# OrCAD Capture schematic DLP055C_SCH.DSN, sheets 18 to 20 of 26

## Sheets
18 P08 - DLPC MISC: size A3
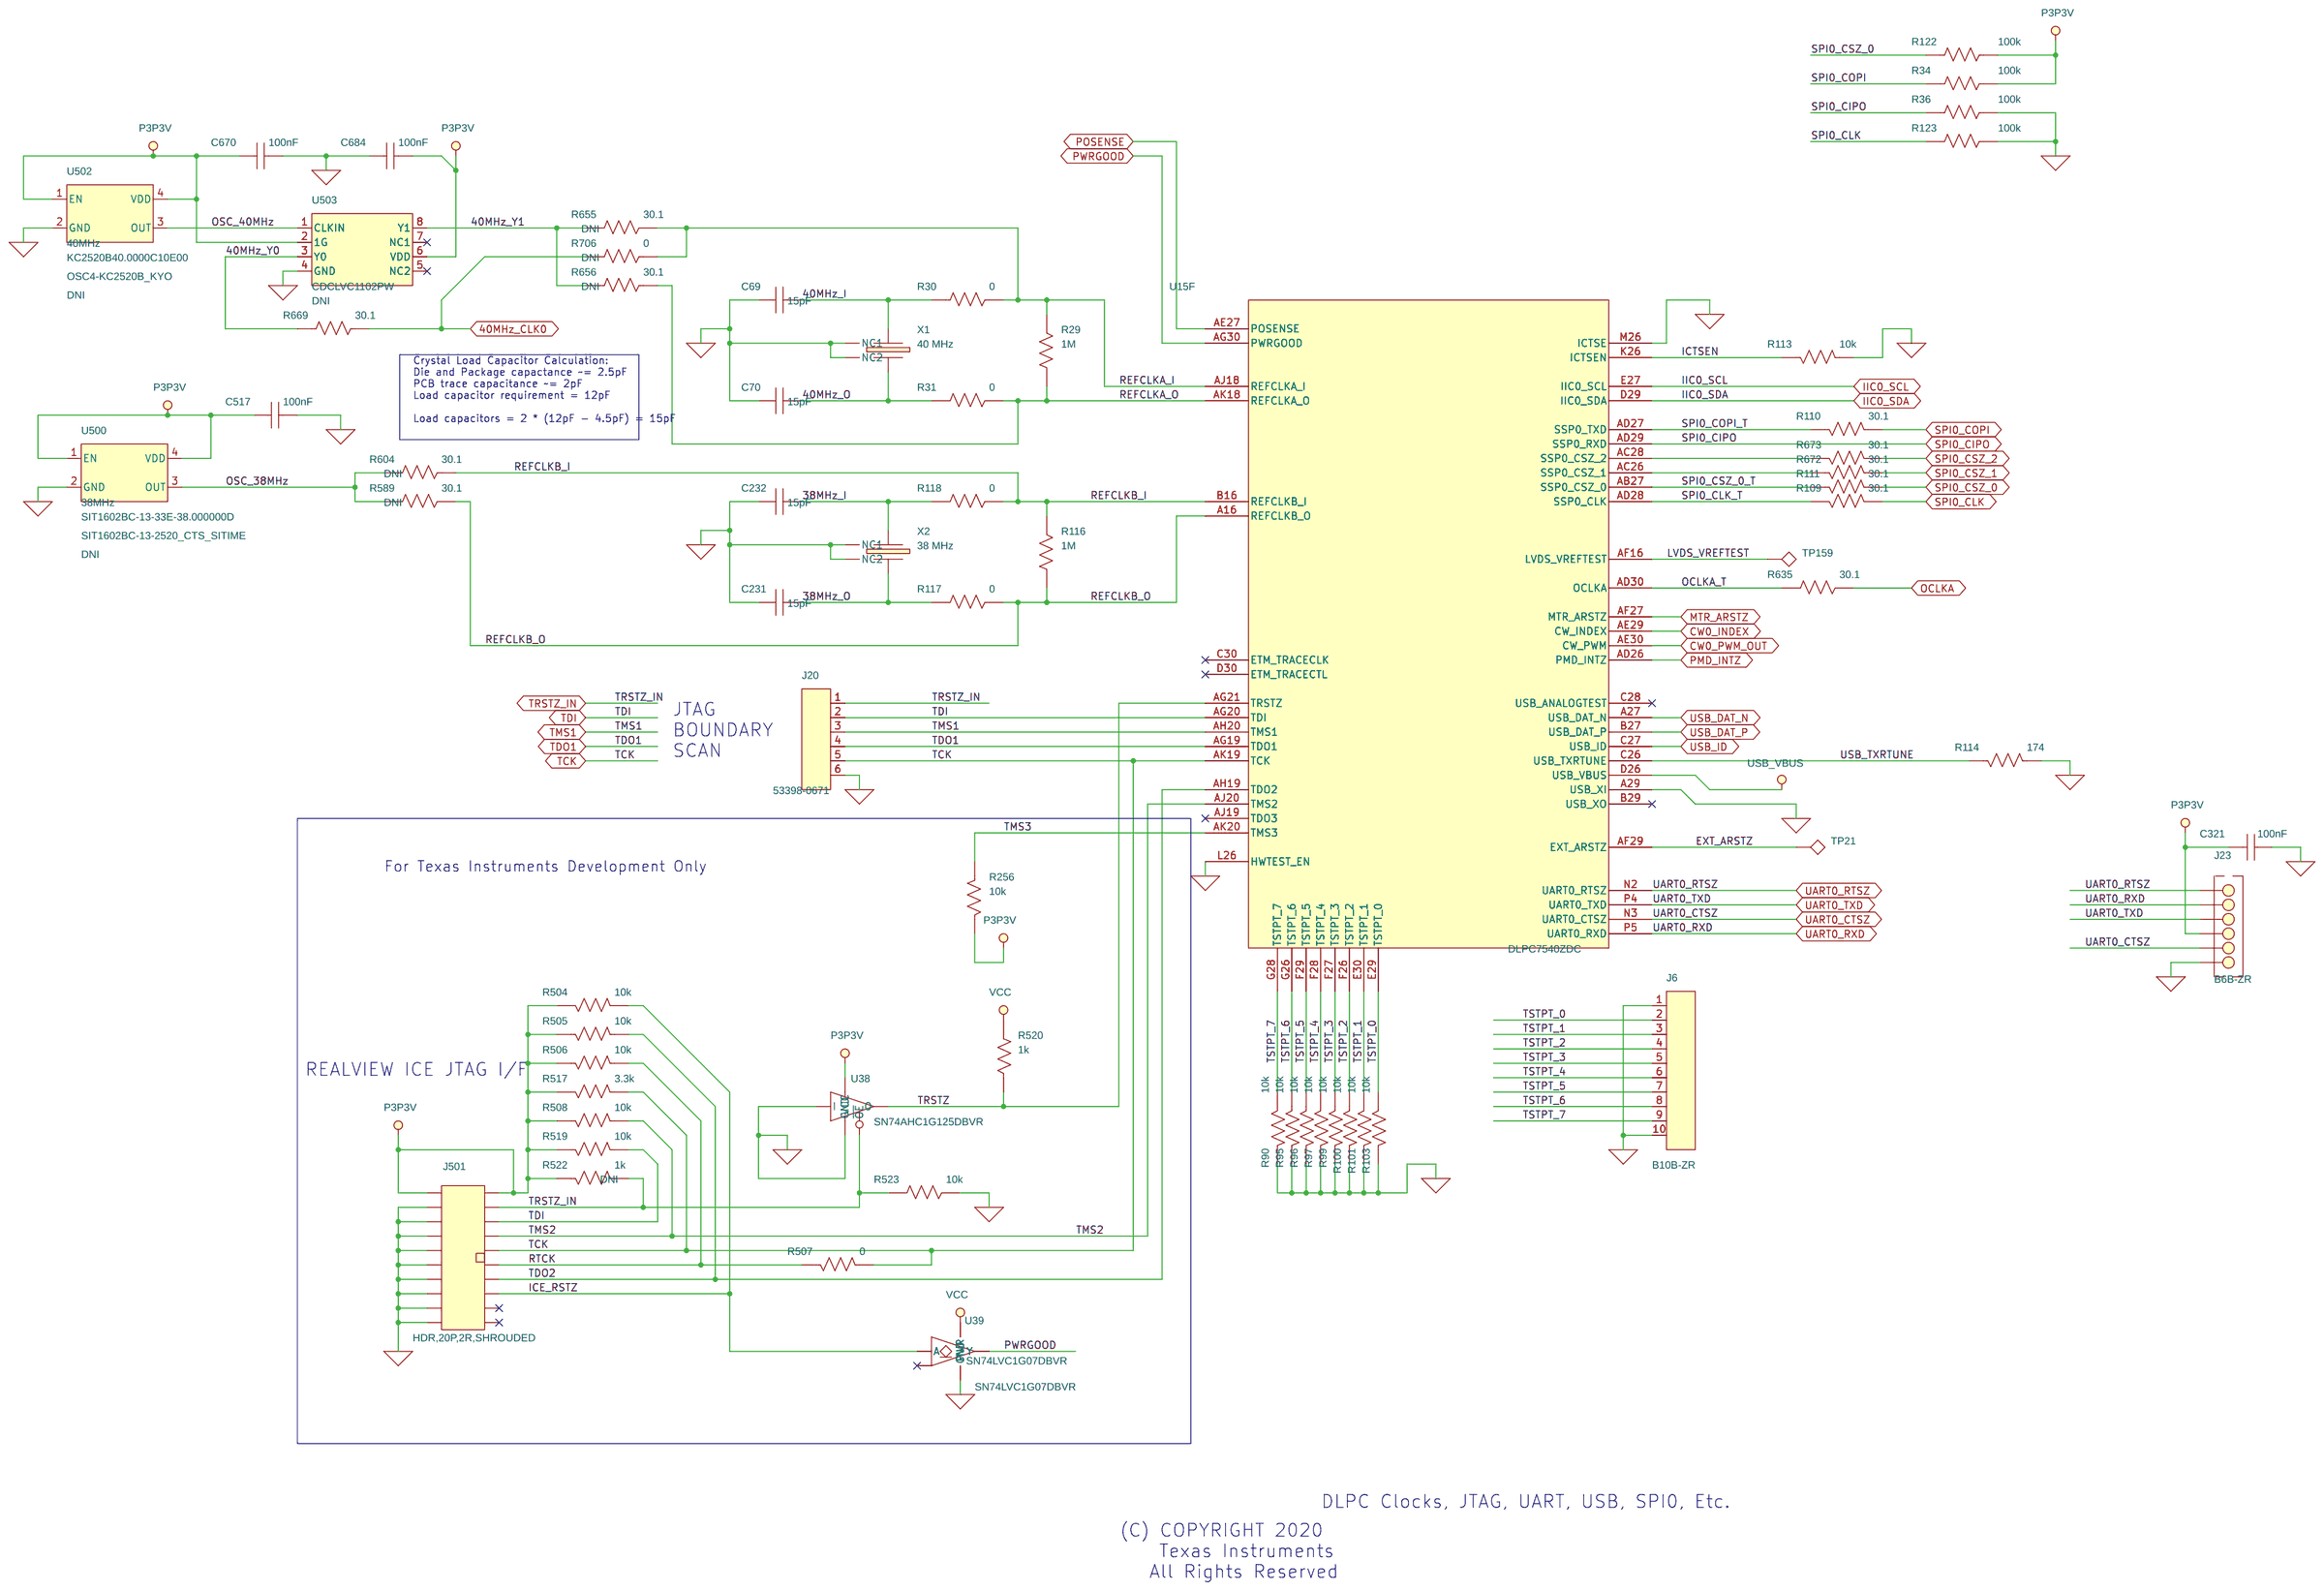
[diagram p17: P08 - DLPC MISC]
19 P12 - IIC, SPI, USB & EEPROM: size A3
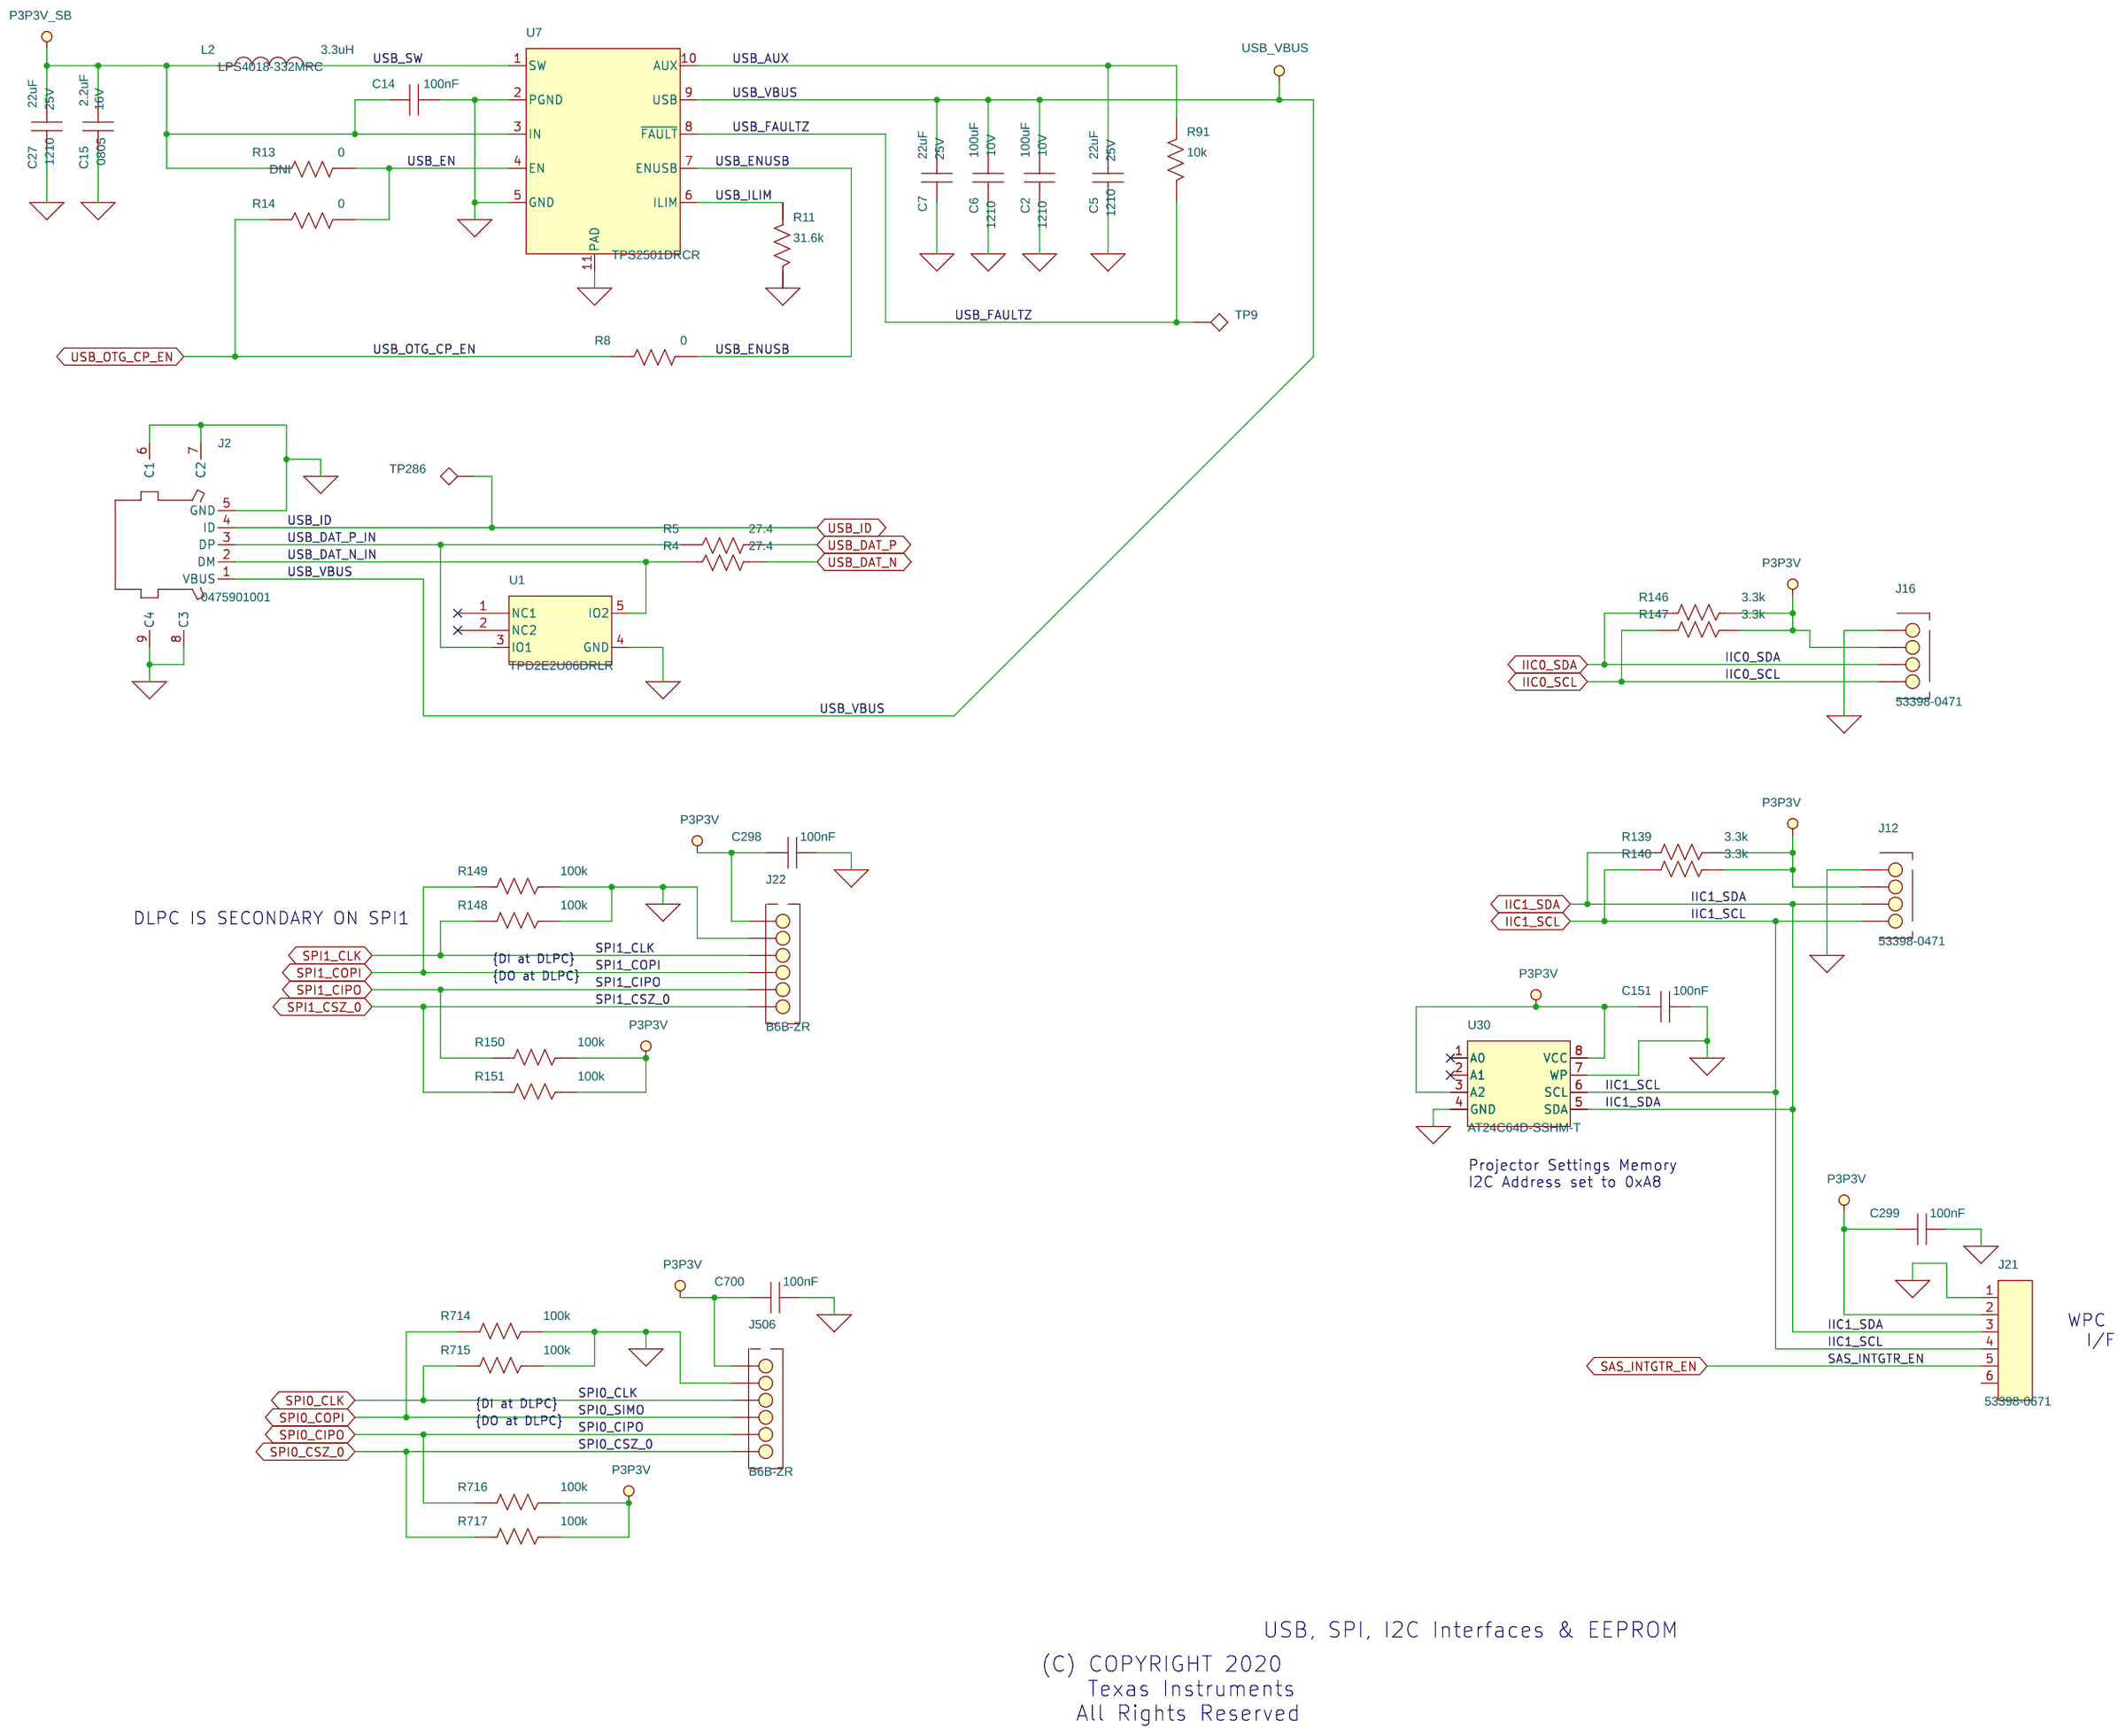
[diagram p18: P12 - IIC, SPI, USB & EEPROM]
20 P09 - DLPC GPIO: size A3
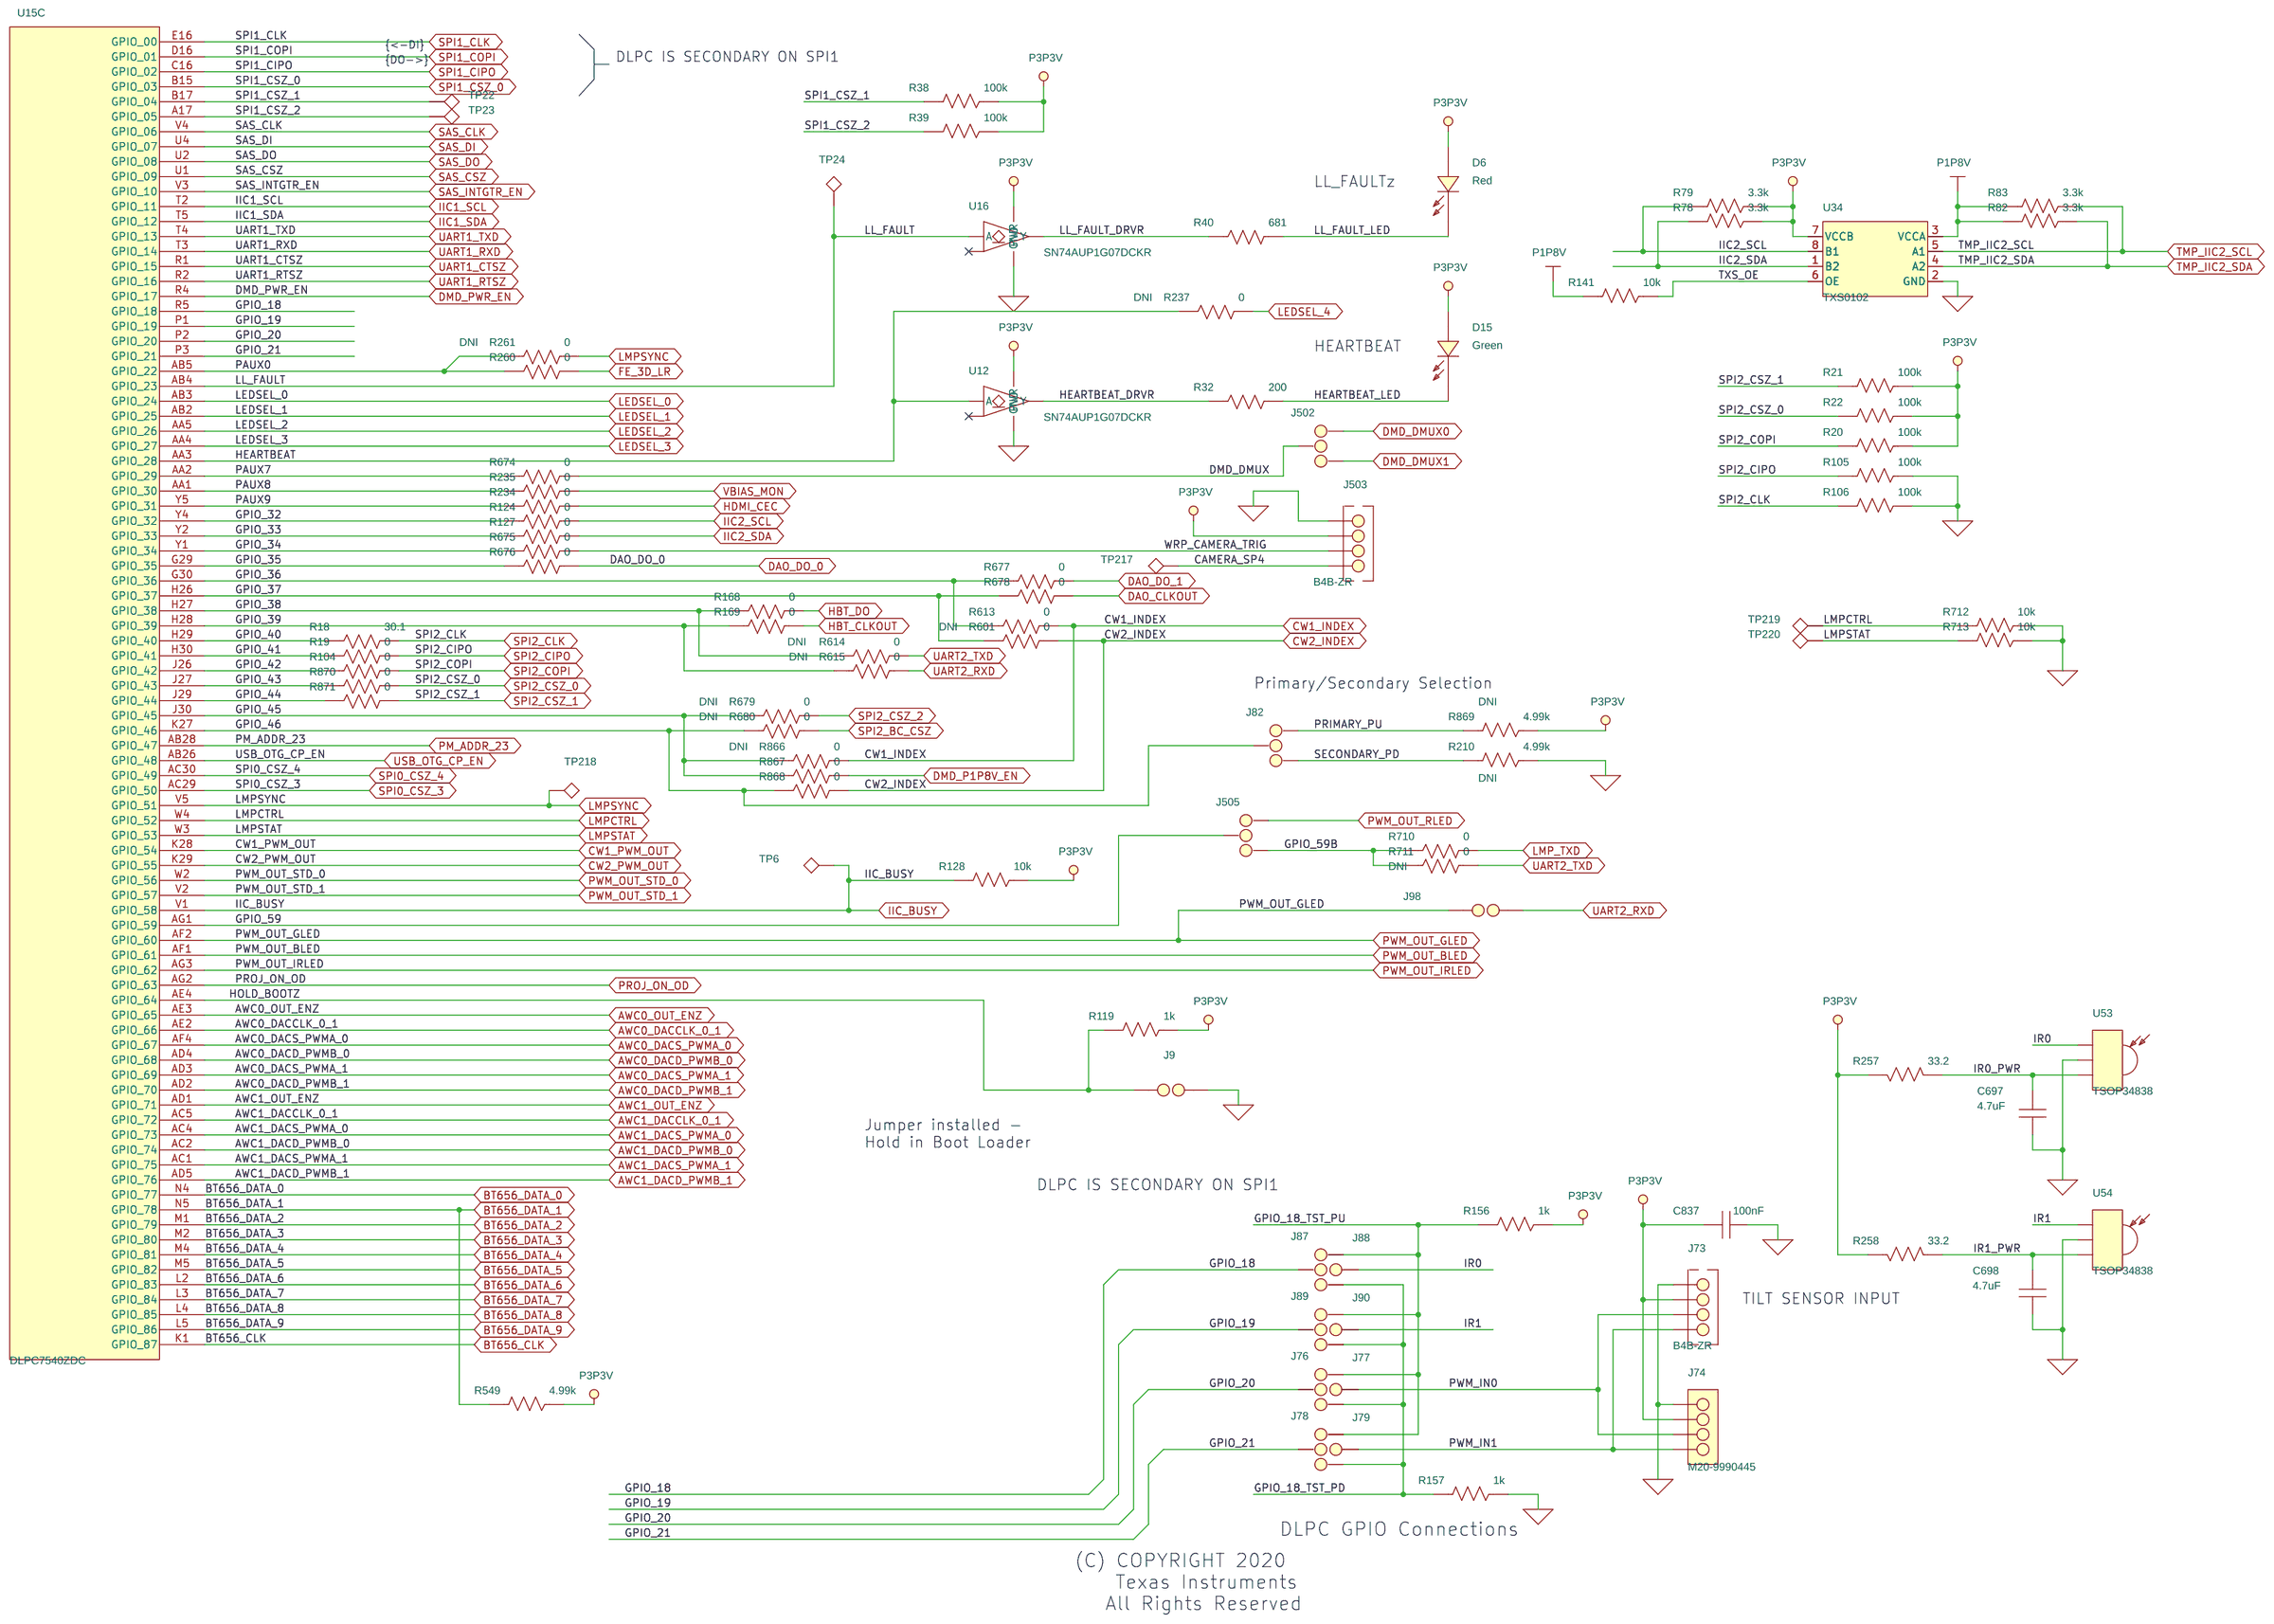
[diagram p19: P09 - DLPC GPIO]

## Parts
sheet P08 - DLPC MISC
C69  15pF  [0402]
C70  15pF  [0402]
C231  15pF  [0402]
C232  15pF  [0402]
C321  100nF  [0402]
C517  100nF  [0402]
C670  100nF  [0402]
C684  100nF  [0402]
J6  B10B-ZR  [JST_B10B-ZR]
J20  53398-0671  [CONN6-53398-0690_MOLEX]
J23  B6B-ZR  [HDR1X6-B6B-ZR_JST]
J501  HDR,20P,2R,SHROUDED  [HDR10X2-5103308_TYCO]
R29  1M  [0402]
R30  0  [0402]
R31  0  [0402]
R34  100k  [0402]
R36  100k  [0402]
R90  10k  [0402]
R95  10k  [0402]
R96  10k  [0402]
R97  10k  [0402]
R99  10k  [0402]
R100  10k  [0402]
R101  10k  [0402]
R103  10k  [0402]
R109  30.1  [0402]
R110  30.1  [0402]
R111  30.1  [0402]
R113  10k  [0402]
R114  174  [0402]
R116  1M  [0402]
R117  0  [0402]
R118  0  [0402]
R122  100k  [0402]
R123  100k  [0402]
R256  10k  [0402]
R504  10k  [0402]
R505  10k  [0402]
R506  10k  [0402]
R507  0  [0402]
R508  10k  [0402]
R517  3.3k  [0402]
R519  10k  [0402]
R520  1k  [0402]
R522  1k  [0402]
R523  10k  [0402]
R589  30.1  [0402]
R604  30.1  [0402]
R635  30.1  [0402]
R655  30.1  [0402]
R656  30.1  [0402]
R669  30.1  [0402]
R672  30.1  [0402]
R673  30.1  [0402]
R706  0  [0402]
TP21  TP,28mil Drill,48mil Pad  [HTP-48RD28]
TP159  TP,28mil Drill,48mil Pad  [HTP-48RD28]
U38  SN74AHC1G125DBVR  [SOIC5-SOT-23_DBV-TI]
U39  SN74LVC1G07DBVR  [SOIC5-SOT-23_DBV-TI]
U500  38MHz  [SIT1602BC-13-2520_CTS_SITIME]
U502  40MHz  [OSC4-KC2520B_KYO]
U503  CDCLVC1102PW  [SOIC8-PW_TI]
X1  40 MHz  [TXC_TM3225]
X2  38 MHz  [TXC_TM3225]
sheet P09 - DLPC GPIO
C697  4.7uF  [0805]
C698  4.7uF  [0805]
C837  100nF  [0402]
D6  Red  [LED-LTST-C190_LITEON]
D15  Green  [LED-LTST-C190_LITEON]
J9  HDR,2P,1R  [HDR2P_1R]
J73  B4B-ZR  [HDR1X4-B4B-ZR_JST]
J74  HDR,4P,1R  [HDR1X4]
J76  HDR,3P,1R  [HDR1X3]
J77  HDR,1P,1R  [HDR1]
J78  HDR,3P,1R  [HDR1X3]
J79  HDR,1P,1R  [HDR1]
J82  HDR,3P,1R  [HDR1X3]
J87  HDR,3P,1R  [HDR1X3]
J88  HDR,1P,1R  [HDR1]
J89  HDR,3P,1R  [HDR1X3]
J90  HDR,1P,1R  [HDR1]
J98  HDR,2P,1R  [HDR2P_1R]
J502  HDR,3P,1R  [HDR1X3]
J503  B4B-ZR  [HDR1X4-B4B-ZR_JST]
J505  HDR,3P,1R  [HDR1X3]
R18  30.1  [0402]
R19  0  [0402]
R20  100k  [0402]
R21  100k  [0402]
R22  100k  [0402]
R32  200  [0402]
R38  100k  [0402]
R39  100k  [0402]
R40  681  [0402]
R78  3.3k  [0402]
R79  3.3k  [0402]
R82  3.3k  [0402]
R83  3.3k  [0402]
R104  0  [0402]
R105  100k  [0402]
R106  100k  [0402]
R119  1k  [0402]
R124  0  [0402]
R127  0  [0402]
R128  10k  [0402]
R141  10k  [0402]
R156  1k  [0402]
R157  1k  [0402]
R168  0  [0402]
R169  0  [0402]
R210  4.99k  [0402]
R234  0  [0402]
R235  0  [0402]
R237  0  [0402]
R257  33.2  [0402]
R258  33.2  [0402]
R260  0  [0402]
R261  0  [0402]
R549  4.99k  [0402]
R601  0  [0402]
R613  0  [0402]
R614  0  [0402]
R615  0  [0402]
R674  0  [0402]
R675  0  [0402]
R676  0  [0402]
R677  0  [0402]
R678  0  [0402]
R679  0  [0402]
R680  0  [0402]
R710  0  [0402]
R711  0  [0402]
R712  10k  [0402]
R713  10k  [0402]
R866  0  [0402]
R867  0  [0402]
R868  0  [0402]
R869  4.99k  [0402]
R870  0  [0402]
R871  0  [0402]
TP6  TP,28mil Drill,48mil Pad  [HTP-48RD28]
TP22  TP,20mil PAD  [20mil_PAD]
TP23  TP,20mil PAD  [20mil_PAD]
TP24  TP,28mil Drill,48mil Pad  [HTP-48RD28]
TP217  TP,20mil PAD  [20mil_PAD]
TP218  TP,28mil Drill,48mil Pad  [HTP-48RD28]
TP219  TP,28mil Drill,48mil Pad  [HTP-48RD28]
TP220  TP,28mil Drill,48mil Pad  [HTP-48RD28]
U12  SN74AUP1G07DCK  [U_5_DCK]
U15  TIDLP,DLPC7540  [DLPC7540_HBGA676_3131]  (sections A,B,C,D,E,F,G,H,I)
U16  SN74AUP1G07DCK  [U_5_DCK]
U34  TXS0102  [VSSOP-8_DCU]
U53  TSOP34838  [IR3-TSOP34_VIS]
U54  TSOP34838  [IR3-TSOP34_VIS]
sheet P12 - IIC, SPI, USB & EEPROM
C2  100uF  [1210]
C5  22uF  [1210]
C6  100uF  [1210]
C7  22uF  [1210]
C14  100nF  [0402]
C15  2.2uF  [0805]
C27  22uF  [1210]
C151  100nF  [0402]
C298  100nF  [0402]
C299  100nF  [0402]
C700  100nF  [0402]
J2  USB,TYPE AB,MICRO,TOP MNT  [Molex_0475901001]
J12  53398-0471  [CONN4-53398_MOLEX]
J16  53398-0471  [CONN4-53398_MOLEX]
J21  53398-0671  [CONN6-53398-0690_MOLEX]
J22  B6B-ZR  [HDR1X6-B6B-ZR_JST]
J506  B6B-ZR  [HDR1X6-B6B-ZR_JST]
L2  3.3uH  [Coilcraft_LPS4018]
R4  27.4  [0402]
R5  27.4  [0402]
R8  0  [0402]
R11  31.6k  [0402]
R13  0  [0402]
R14  0  [0402]
R91  10k  [0402]
R139  3.3k  [0402]
R140  3.3k  [0402]
R146  3.3k  [0402]
R147  3.3k  [0402]
R148  100k  [0402]
R149  100k  [0402]
R150  100k  [0402]
R151  100k  [0402]
R714  100k  [0402]
R715  100k  [0402]
R716  100k  [0402]
R717  100k  [0402]
TP9  TP,28mil Drill,48mil Pad  [HTP-48RD28]
TP286  TP,28mil Drill,48mil Pad  [HTP-48RD28]
U1  TPD2E2U06DRL  [SOT-5_DRL_R-PDSO-N5]
U7  TPS2501DRCR  [TI_DRC0010J_VSON-10]
U30  AT24C64D-SSHM-T  [SOIC8]

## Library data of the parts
C69 C70 C231 C232 = PAS,CAP,NP: ALT_SYMBOLS: 0402_1mm; CCA: 9; DigiKey: 1276-1179-1-ND; DigiReel: 1276-1179-6-ND; Family: passive; Index PN: 1567; Install: Y; Lead Style: SMT; MFG: Samsung; Material: npo; P/D_NUM: CL05C150JB5NNNC; Part Number: CL05C150JB5NNNC; Part Specific: CAP CER 15PF 50V C0G/NP0 0402; TOLERANCE: 5%; Type: capacitor; VPC: 50V; Vendor: Samsung; Voltage: 50V
C14 C151 C298 C299 C321 C700 = PAS,CAP,NP: ALT_SYMBOLS: 0402_1mm; DigiKey: 587-3499-1-ND; DigiReel: 587-3499-6-ND; Family: passive; Index PN: 1280; Install: Y; Lead Style: SMT; MFG: Taiyo Yuden; Material: x5r; P/D_NUM: UMK105BJ104KV-F; Part Number: UMK105BJ104KV-F; Part Specific: CAP CER 0.1UF 50V 10% X5R 0402; TOLERANCE: 10%; Type: capacitor; VPC: 50V; Vendor: Taiyo Yuden
C517 = PAS,CAP,NP: ALT_SYMBOLS: 0402_1mm; CCA: 9; DigiKey: 587-3499-1-ND; Family: passive; Index PN: 1280; Install: Y; Lead Style: SMT; MFG: Taiyo Yuden; Material: x5r; P/D_NUM: UMK105BJ104KV-F; Part Number: UMK105BJ104KV-F; Part Specific: CAP CER 0.1UF 50V 10% X5R 0402; RATING: <RATING>; TOLERANCE: 10%; Type: capacitor; VPC: 50V; Vendor: Taiyo Yuden
C670 C684 = PAS,CAP,NP: ALT_SYMBOLS: 0402_1mm; CCA: 9; DigiKey: 587-3499-1-ND; Family: passive; Index PN: 1280; Install: Y; Lead Style: SMT; MFG: Taiyo Yuden; Material: x5r; P/D_NUM: UMK105BJ104KV-F; Part Number: UMK105BJ104KV-F; Part Specific: CAP CER 0.1UF 50V 10% X5R 0402; TOLERANCE: 10%; Type: capacitor; VPC: 50V; Vendor: Taiyo Yuden
J6 = EM,HDR,10P,1R: DigiKey: 455-1665-ND; Family: electro/mechanical; Index PN: 1120; Install: Y; Lead Style: TH; MFG: JST; P/D_NUM: B10B-ZR(LF)(SN); Part Number: B10B-ZR(LF)(SN); Part Specific: CONN HEADER ZH TOP 10POS 1.5MM; Pin Cnt: 10; Pin Spacing: 1.5mm; Row Cnt: 1; Vendor: JST
J20 J21 = EM,HDR,6P,1R: DigiKey: WM7610CT-ND; DigiReel: WM7610DKR-ND; Family: electro/mechanical; Index PN: 1521; Install: Y; Lead Style: SMT; MFG: Molex; Part Specific: CONN HEADER 6POS 1.25MM VERT SMD; Pin Cnt: 6; Pin Spacing: 1.25mm; Row Cnt: 1; Type: connector; Vendor: Molex
J23 = EM,HDR,6P,1R,1x,B6B-EH: DigiKey: 455-1661-ND; DigiReel: ---; Family: electro/mechanical; Index PN: 1663; Lead Style: TH; MFG: JST; P/D_NUM: B6B-ZR(LF)(SN); Part Number: B6B-ZR(LF)(SN); Part Specific: CONN HEADER VERT 6POS 1.5MM; Pin Cnt: 6; Pin Spacing: 1.5mm; Row Cnt: 1; Type: connector; Vendor: JST
J501 = EM,HDR,20P,2R,NARROW_SYM: DigiKey: A33165-ND; Family: electro/mechanical; Index PN: 1093; Lead Style: TH; MFG: Tyco Electronics; P/D_NUM: 5103308-5; Part Number: 5103308-5; Part Specific: CONN HEADER LOPRO STR 14POS GOLD; Pin Cnt: 14; Pin Spacing: 100x100mil; Row Cnt: 2; Type: header; Vendor: Tyco Electronics
R29 R116 = PAS,R,large: ALT_SYMBOLS: 0402_1mm; DigiKey: P1.00MLCT-ND; Family: passive; Index PN: 1229; Lead Style: SMT; MFG: Panasonic; Material: chip; P/D_NUM: ERJ-2RKF1004X; Part Number: ERJ-2RKF1004X; Part Specific: RES 1M OHM 1/10W 1% 0402 SMD; TOLERANCE: 1%; Type: resistor; VENDOR: Panasonic; VPC: 1/10W
R30 R31 R117 R118 = PAS,R,large: ALT_SYMBOLS: 0402_1mm; DigiKey: P0.0JCT-ND; DigiReel: P0.0JDKR-ND; Family: passive; Index PN: 687; Lead Style: SMT; MFG: Panasonic; Material: chip; P/D_NUM: ERJ-2GE0R00X; Part Number: ERJ-2GE0R00X; Part Specific: RES 0.0 OHM 1/16W 0402 SMD; Power: 1/16W; Type: resistor; VENDOR: Panasonic; VPC: 1/16W
R20-R22 R34 R36 R38 R39 R105 R106 R122 R123 R148-R151 R714-R717 = PAS,R,large: ALT_SYMBOLS: 0402_1mm; DigiKey: 311-100KLRCT-ND; DigiReel: 311-100KLRDKR-ND; Family: passive; Lead Style: SMT; MFG: Yageo; Material: chip; P/D_NUM: RC0402FR-07100KL; Part Number: RC0402FR-07100KL; Part Specific: RES 100K OHM 1/10W 1% 0402 SMD; Power: 1/16W; Tolerance: 1%; Type: resistor; VPC: 1/16W; Vendor: Yageo
R90 R91 R95-R97 R99-R101 R103 R113 = PAS,R,large: ALT_SYMBOLS: 0402_1mm; CCA: 65; DigiKey: 311-10.0KLRCT-ND; DigiReel: 311-10.0KLRDKR-ND; Family: passive; ICA_MFR_NAME: PANASONIC; ICA_PARTNUM: $$1785048$$ERJ-3GSYJ102; Index PN: 680; Install: Y; Lead Style: SMT; MFG: Yageo; Material: chip; P/D_NUM: RC0402FR-0710KL; Part Number: RC0402FR-0710KL; Part Specific: RES 10K OHM 1% 1/16W 0402 SMD; Power: 1/16W; TOLERANCE: 1%; Type: resistor; VPC: 1/16W; Vendor: Yageo
R109-R111 R672 R673 = PAS,R,large: ALT_SYMBOLS: 0402_1mm; DigiKey: YAG3111CT-ND; Family: passive; Index PN: 976; Lead Style: SMT; MFG: Yageo; Material: chip; P/D_NUM: RC0402FR-0730R1L; Part Number: RC0402FR-0730R1L; Part Specific: RES 30.1 OHM 1/16W 1% 0402 SMD; Power: 1/16W; TOLERANCE: 1%; Type: resistor; VENDOR: Yageo; VPC: 1/16W
R114 = PAS,R,large: ALT_SYMBOLS: 0402_1mm; DigiKey: YAG3009CT-ND; DigiReel: YAG3009DKR-ND; Family: passive; Index PN: 1701; Lead Style: SMT; MFG: Yageo; P/D_NUM: RC0402FR-07174RL; Part Number: RC0402FR-07174RL; Part Specific: RES 174 OHM 1% 1/16W 0402 SMD; TOLERANCE: 1%; Type: resistor; VENDOR: Yageo; VPC: 1/16W
R256 R504-R506 R508 R519 R523 = PAS,R,large: ALT_SYMBOLS: 0402_1mm; CCA: 65; DigiKey: 311-10.0KLRCT-ND; Family: passive; ICA_MFR_NAME: PANASONIC; ICA_PARTNUM: $$1785048$$ERJ-3GSYJ102; Index PN: 680; Install: Y; Lead Style: SMT; MFG: Yageo; Material: chip; P/D_NUM: RC0402FR-0710KL; Part Number: RC0402FR-0710KL; Power: 1/16W; TOLERANCE: 1%; Type: resistor; VPC: 1/16W; Vendor: Yageo
R507 = PAS,R,large: ALT_SYMBOLS: 0402_1mm; CCA: 64; DigiKey: P0.0JCT-ND; Family: passive; ICA_MFR_NAME: PANASONIC; ICA_PARTNUM: $$1785048$$ERJ-3GSYJ102; Index PN: 687; Install: Y; Lead Style: SMT; MFG: Panasonic; Material: chip; P/D_NUM: ERJ-2GE0R00X; Part Number: ERJ-2GE0R00X; Part Specific: RES 0.0 OHM 1/16W 0402 SMD; Power: 1/16W; Type: resistor; VPC: 1/16W; Vendor: Panasonic
R517 = PAS,R,large: ALT_SYMBOLS: 0402_1mm; CCA: 68; DigiKey: P3.3KDCCT-ND; Family: passive; ICA_MFR_NAME: PANASONIC; ICA_PARTNUM: $$1785048$$ERJ-3GSYJ102; Index PN: 1436; Install: Y; Lead Style: SMT; MFG: Panasonic; Material: chip; P/D_NUM: ERA-2AEB332X; Part Number: ERA-2AEB332X; Part Specific: RES SMD 3.3K OHM 0.1% 1/16W 0402; TOLERANCE: 1%; Type: resistor; VPC: 1/16W; Vendor: Panasonic
R520 = PAS,R,large: ALT_SYMBOLS: 0402_1mm; CCA: 64; DigiKey: 311-1.00KLRCT-ND; Family: passive; ICA_MFR_NAME: PANASONIC; ICA_PARTNUM: $$1785048$$ERJ-3GSYJ102; Index PN: 684; Install: Y; Lead Style: SMT; MFG: Yageo; Material: chip; P/D_NUM: RC0402FR-071KL; Part Number: RC0402FR-071KL; Part Specific: RES 1.00K OHM 1/10W 1% 0402 SMD; Power: 1/16W; TOLERANCE: 1%; Type: resistor; VPC: 1/16W; Vendor: Yageo
R522 = PAS,R,large: ALT_SYMBOLS: 0402_1mm; CCA: 64; DigiKey: 311-1.00KLRCT-ND; Family: passive; ICA_MFR_NAME: PANASONIC; ICA_PARTNUM: $$1785048$$ERJ-3GSYJ102; Index PN: 684; Install: DNI; Lead Style: SMT; MFG: Yageo; Material: chip; P/D_NUM: RC0402FR-071KL; Part Number: RC0402FR-071KL; Part Specific: RES 1.00K OHM 1/10W 1% 0402 SMD; Power: 1/16W; TOLERANCE: 1%; Type: resistor; VPC: 1/16W; Vendor: Yageo
R589 R604 R655 R656 = PAS,R,large: ALT_SYMBOLS: 0402_1mm; DigiKey: YAG3111CT-ND; Family: passive; Index PN: 976; Install: DNI; Lead Style: SMT; MFG: Yageo; Material: chip; P/D_NUM: RC0402FR-0730R1L; Part Number: RC0402FR-0730R1L; Part Specific: RES 30.1 OHM 1/16W 1% 0402 SMD; Power: 1/16W; TOLERANCE: 1%; Type: resistor; VENDOR: Yageo; VPC: 1/16W
R635 = PAS,R,large: ALT_SYMBOLS: 0402_1mm; CCA: 67; DigiKey: YAG3111CT-ND; Family: passive; ICA_MFR_NAME: PANASONIC; ICA_PARTNUM: $$1785048$$ERJ-3GSYJ102; Index PN: 976; Install: Y; Lead Style: SMT; MFG: Yageo; Material: chip; P/D_NUM: RC0402FR-0730R1L; Part Number: RC0402FR-0730R1L; Part Specific: RES 30.1 OHM 1/16W 1% 0402 SMD; Power: 1/16W; TOLERANCE: 1%; Type: resistor; VPC: 1/16W; Vendor: Yageo
R669 = PAS,R,large: ALT_SYMBOLS: 0402_1mm; DigiKey: YAG3111CT-ND; Family: passive; Index PN: 976; Install: Y; Lead Style: SMT; MFG: Yageo; Material: chip; P/D_NUM: RC0402FR-0730R1L; Part Number: RC0402FR-0730R1L; Part Specific: RES 30.1 OHM 1/16W 1% 0402 SMD; Power: 1/16W; TOLERANCE: 1%; Type: resistor; VENDOR: Yageo; VPC: 1/16W
R706 = PAS,R,large: ALT_SYMBOLS: 0402_1mm; DigiKey: P0.0JCT-ND; Family: passive; Index PN: 687; Install: DNI; Lead Style: SMT; MFG: Panasonic; Material: chip; P/D_NUM: ERJ-2GE0R00X; Part Number: ERJ-2GE0R00X; Part Specific: RES 0.0 OHM 1/16W 0402 SMD; Power: 1/16W; Type: resistor; VENDOR: Panasonic; VPC: 1/16W
TP6 TP9 TP21 TP24 TP159 TP218-TP220 TP286 = EM,TERM,TESTPOINT: DigiKey: ---; Family: board feature; Index PN: 1498; Install: DNI; Lead Style: TH; MFG: -- NOT A PART --; Part Specific: HOLE PLATED 48mil pad 28mil drill; Type: hole,plated; Vendor: -- NOT A PART --
U38 = LOG,BUF,74LVC1G125,1x: DigiKey: 296-8744-1-ND; Family: logic; Index PN: 648; Install: Y; MFG: Texas Instruments; Part Specific: Buffer Non-Inverting 1 Element 1 Bit per Element Push-Pull Output SOT-23-5; Type: transceiver; Vendor: Texas Instruments
U39 = TMP_30: CCA: 147; DigiKey: 296-8485-1-ND; Family: logic; Index PN: 1491; Install: Y; Lead Style: SMT; MFG: Texas Instruments; Part Specific: IC BUFF/DVR NON-INVERT SOT23-5; Type: buffer; Vendor: Texas Instruments
U500 = ANA,OSC,4P,1X,small: DigiKey: 1473-SIT1602BC-13-33E-38.000000D-ND; Family: analog; Index PN: 1768; Install: DNI; Lead Style: SMT; MFG: CTS; P/D_NUM: SIT1602BC-13-33E-38.000000D; Part Number: SIT1602BC-13-33E-38.000000D; Part Specific: TCXO Oscillators 38.4MHz 3.3Volt +/-1.5ppm -40C +85C; Type: oscillator; Vendor: SiTIME
U502 = ANA,OSC,4P,1X,small: DigiKey: 478-6300-1-ND; Family: analog; Index PN: 1660; Install: DNI; Lead Style: SMT; MFG: Kyocera; P/D_NUM: KC2520B40.0000C10E00; Part Number: KC2520B40.0000C10E00; Part Specific: XTAL OSC XO 40.0000MHZ CMOS SMD; Type: oscillator; Vendor: Kyocera
U503 = INF,CLK_DRVR,CDCLVC1102: DigiKey: 296-27610-1-ND; Family: interface; Index PN: 1477; Install: DNI; Lead Style: SMT; MFG: Texas Instruments; Part Specific: IC CLK BUFFER 1:2 250MHZ 8TSSOP; Type: clock driver; Vendor: Texas Instruments
X1 = 7V-40.000MDDE-T_CUS: DigiKey: ---; DigiReel: ---; Family: passive; Lead Style: SMT; MFG: TXC; Mouser: ---; P/D_NUM: 7V-40.000MDDE-T; Part Number: 7V-40.000MDDE-T; Part Specific: 40 MHZ, 12pF, +/-20PPM/C, SMD-4P; Type: crystal; VENDOR: TXC
X2 = 7V-38.000MAAV-T_CUS: DigiKey: ---; DigiReel: ---; Family: passive; Lead Style: SMT; MFG: TXC; Mouser: ---; P/D_NUM: 7V-38.000MAAV-T; Part Number: 7V-38.000MAAV-T; Part Specific: 38 MHZ, 8pF, +/-30PPM/C, SMD-4P; Type: crystal; VENDOR: TXC
C697 C698 = PAS,CAP,NP: CCA: 42; DigiKey: 1276-1244-1-ND; Family: passive; Index PN: 1400; Install: Y; Lead Style: SMT; MFG: Samsung; Material: x5r; P/D_NUM: CL21A475KAQNNNE; Part Number: CL21A475KAQNNNE; Part Specific: CAP CER 4.7UF 25V X5R 0805; TOLERANCE: 10%; Type: capacitor; VPC: 25V; Vendor: Samsung
C837 = PAS,CAP,NP: ALT_SYMBOLS: 0402_1mm; CCA: 5; DigiKey: 587-3499-1-ND; Family: passive; Index PN: 1280; Install: Y; Lead Style: SMT; MFG: Taiyo Yuden; Material: x5r; P/D_NUM: UMK105BJ104KV-F; Part Number: UMK105BJ104KV-F; Part Specific: CAP CER 0.1UF 50V 10% X5R 0402; TOLERANCE: 10%; Type: capacitor; VPC: 50V; Vendor: Taiyo Yuden
D6 = PAS,DIODE,LED,ALT: DigiKey: 160-1447-1-ND; Family: passive; Index PN: 1452; Install: Y; Lead Style: SMT; MFG: Liteon; P/D_NUM: LTST-C191KRKT; Part Number: LTST-C191KRKT; Part Specific: LED RED CLEAR 0603 SMD; Type: diode,led; Vendor: Liteon
D15 = PAS,DIODE,LED,ALT: DigiKey: 160-1183-1-ND; Family: passive; Index PN: 1451; Install: Y; Lead Style: SMT; MFG: Liteon; P/D_NUM: LTST-C190GKT; Part Number: LTST-C190GKT; Part Specific: LED GREEN CLEAR 0603 SMD; Type: diode,led; Vendor: Liteon
J9 = EM,JMP,2P,1R: DigiKey: 952-2261-ND; Index PN: 180; Lead Style: TH; MFG: Harwin; P/D_NUM: M20-9990245; Part Number: M20-9990245; Part Specific: CONN HEADER VERT 2POS 2.54MM; Pin Cnt: 2; Pin Spacing: 100mil; Row Cnt: 1; Type: header; Vendor: Harwin
J73 J503 = EM,HDR,4P,1R,1x,B4B-EH: DigiKey: 455-1659-ND; Family: electro/mechanical; Index PN: 1664; Lead Style: TH; MFG: JST; P/D_NUM: B4B-ZR(LF)(SN); Part Number: B4B-ZR(LF)(SN); Part Specific: CONN HEADER VERT 4POS 1.5MM; Pin Cnt: 4; Pin Spacing: 1.5mm; Row Cnt: 1; Type: header; Vendor: JST
J74 = EM,HDR,4P,1R,1x,NARROW: DigiKey: 952-2265-ND; Family: electro/mechanical; Index PN: 819; Lead Style: TH; MFG: Harwin; P/D_NUM: M20-9990445; Part Number: M20-9990445; Part Specific: 4 Positions Header  Unshrouded  Breakaway Connector 0.100in (2.54mm) Through Hole Gold; Pin Cnt: 4; Pin Spacing: 100mil; Row Cnt: 1; Type: header; Vendor: Harwin
J76 J78 J87 J89 J502 J505 = EM,JMP,3P,1R,1X,ALT: DigiKey: 952-2263-ND; Index PN: 20; Lead Style: TH; MFG: Harwin; P/D_NUM: M20-9990345; Part Number: M20-9990345; Part Specific: 3 Positions Header  Unshrouded  Breakaway Connector 0.100in (2.54mm) Through Hole Gold; Pin Cnt: 3; Pin Spacing: 100mil; Row Cnt: 1; Type: header; Vendor: Harwin
J77 J79 J88 J90 = EM,JMP,1P,1R,2: DigiKey: SAM1029-01-ND; Family: electro/mechanical; Index PN: 896; Lead Style: TH; MFG: Samtec; P/D_NUM: TSW-101-07-G-S; Part Number: TSW-101-07-G-S; Part Specific: CONN HEADER 1POS .100in. SGL GOLD; Pin Cnt: 1; Pin Spacing: 100mil; Row Cnt: 1; Type: header; Vendor: Samtec
J82 = EM,JMP,3P,1R,1X,ALT: DigiKey: 952-2263-ND; Index PN: 20; Install: Y; Lead Style: TH; MFG: Harwin; P/D_NUM: M20-9990345; Part Number: M20-9990345; Part Specific: 3 Positions Header  Unshrouded  Breakaway Connector 0.100in (2.54mm) Through Hole Gold; Pin Cnt: 3; Pin Spacing: 100mil; Row Cnt: 1; Type: header; Vendor: Harwin
J98 = EM,JMP,2P,1R: DigiKey: 952-2261-ND; Index PN: 180; Lead Style: TH; MFG: Harwin; P/D_NUM: M20-9990245; Part Number: M20-9990245; Part Specific: 2 Positions Header  Unshrouded  Breakaway Connector 0.100in (2.54mm) Through Hole Gold; Pin Cnt: 2; Pin Spacing: 100mil; Row Cnt: 1; Type: header; Vendor: Harwin
R18 = PAS,R,large: ALT_SYMBOLS: 0402_1mm; CCA: 62; DigiKey: YAG3111CT-ND; Family: passive; ICA_MFR_NAME: PANASONIC; ICA_PARTNUM: $$1785048$$ERJ-3GSYJ102; Index PN: 976; Install: Y; Lead Style: SMT; MFG: Yageo; Material: chip; P/D_NUM: RC0402FR-0730R1L; Part Number: RC0402FR-0730R1L; Part Specific: RES 30.1 OHM 1/16W 1% 0402 SMD; Power: 1/16W; TOLERANCE: 1%; Type: resistor; VPC: 1/16W; Vendor: Yageo
R8 R14 R19 R104 R124 R127 R870 R871 = PAS,R,large: ALT_SYMBOLS: 0402_1mm; DigiKey: P0.0JCT-ND; DigiReel: P0.0JDKR-ND; Family: passive; ICA_MFR_NAME: PANASONIC; ICA_PARTNUM: $$1785048$$ERJ-3GSYJ102; Index PN: 687; Install: Y; Lead Style: SMT; MFG: Panasonic; Material: chip; P/D_NUM: ERJ-2GE0R00X; Part Number: ERJ-2GE0R00X; Part Specific: RES 0.0 OHM 1/16W 0402 SMD; Power: 1/16W; Type: resistor; VPC: 1/16W; Vendor: Panasonic
R32 = PAS,R,large: DigiKey: P200LCT-ND; DigiReel: P200LDKR-ND; Family: passive; ICA_MFR_NAME: PANASONIC; ICA_PARTNUM: $$1785048$$ERJ-3GSYJ102; Index PN: 1735; Install: Y; Lead Style: SMT; MFG: Panasonic; Material: chip; P/D_NUM: ERJ-2RKF2000X; Part Number: ERJ-2RKF2000X; Part Specific: RES 200 OHM 1% 1/10W 0402 SMD; TOLERANCE: 1%; Type: resistor; VPC: 1/16W; Vendor: Panasonic
R40 = PAS,R,large: ALT_SYMBOLS: 0402_1mm; CCA: 95; DigiKey: P681LCT-ND; Family: passive; ICA_MFR_NAME: PANASONIC; ICA_PARTNUM: $$1785048$$ERJ-3GSYJ102; Index PN: 1119; Install: Y; Lead Style: SMT; MFG: Panasonic; Material: chip; P/D_NUM: ERJ-2RKF6810X; Part Number: ERJ-2RKF6810X; Part Specific: RES 681 OHM 1/10W 1% 0402 SMD; TOLERANCE: 1%; Type: resistor; VPC: 1/10W; Vendor: Panasonic
R78 R79 R82 R83 R139 R140 R146 R147 = PAS,R,large: ALT_SYMBOLS: 0402_1mm; DigiKey: P3.3KJCT-ND; DigiReel: P3.3KJDKR-ND; Family: passive; Lead Style: SMT; MFG: Panasonic; Material: chip; P/D_NUM: ERJ-2GEJ332X; Part Number: ERJ-2GEJ332X; Part Specific: RES 3.3K OHM 5% 1/10W 0402 SMD; Tolerance: 5%; Type: resistor; VPC: 1/10W; Vendor: Panasonic
R119 = PAS,R,large: ALT_SYMBOLS: 0402_1mm; DigiKey: P1.00KLCT-ND; DigiReel: P1.00KLDKR-ND; Family: passive; Index PN: 684; Lead Style: SMT; MFG: Panasonic; Material: chip; P/D_NUM: ERJ-2RKF1001X; Part Number: ERJ-2RKF1001X; Part Specific: RES 1.00K OHM 1/10W 1% 0402 SMD; Power: 1/16W; Tolerance: 1%; Type: resistor; VPC: 1/16W; Vendor: Panasonic
R128 R141 = PAS,R,large: ALT_SYMBOLS: 0402_1mm; DigiKey: 311-10.0KLRCT-ND; DigiReel: 311-10.0KLRDKR-ND; Family: passive; Index PN: 680; Lead Style: SMT; MFG: Yageo; Material: chip; P/D_NUM: RC0402FR-0710KL; Part Number: RC0402FR-0710KL; Part Specific: RES 10K OHM 1% 1/16W 0402 SMD; Power: 1/16W; Tolerance: 1%; Type: resistor; VPC: 1/16W; Vendor: Yageo
R156 R157 = PAS,R,large: ALT_SYMBOLS: 0402_1mm; DigiKey: 311-1.00KLRCT-ND; Family: passive; Index PN: 684; Lead Style: SMT; MFG: Yageo; Material: chip; P/D_NUM: RC0402FR-071KL; Part Number: RC0402FR-071KL; Part Specific: RES 1.00K OHM 1/10W 1% 0402 SMD; Power: 1/16W; Tolerance: 1%; Type: resistor; VPC: 1/16W; Vendor: Yageo
R168 R169 R234 R235 R260 R613 R674-R678 R710 R867 R868 = PAS,R,large: ALT_SYMBOLS: 0402_1mm; CCA: 62; DigiKey: P0.0JCT-ND; Family: passive; ICA_MFR_NAME: PANASONIC; ICA_PARTNUM: $$1785048$$ERJ-3GSYJ102; Index PN: 687; Install: Y; Lead Style: SMT; MFG: Panasonic; Material: chip; P/D_NUM: ERJ-2GE0R00X; Part Number: ERJ-2GE0R00X; Part Specific: RES 0.0 OHM 1/16W 0402 SMD; Power: 1/16W; Type: resistor; VPC: 1/16W; Vendor: Panasonic
R210 R869 = PAS,R,large: ALT_SYMBOLS: 0402_1mm; DigiKey: 311-4.99KLRCT-ND; Family: passive; Index PN: 1129; Install: DNI; Lead Style: SMT; MFG: Yageo; Material: chip; P/D_NUM: RC0402FR-074K99L; Part Number: RC0402FR-074K99L; Part Specific: RES 4.99K OHM 1/10W 1% 0402 SMD; Type: resistor; VPC: 1/16W; Vendor: Yageo
R237 R261 R601 R614 R615 R679 R680 R711 R866 = PAS,R,large: ALT_SYMBOLS: 0402_1mm; CCA: 62; DigiKey: P0.0JCT-ND; Family: passive; ICA_MFR_NAME: PANASONIC; ICA_PARTNUM: $$1785048$$ERJ-3GSYJ102; Index PN: 687; Install: DNI; Lead Style: SMT; MFG: Panasonic; Material: chip; P/D_NUM: ERJ-2GE0R00X; Part Number: ERJ-2GE0R00X; Part Specific: RES 0.0 OHM 1/16W 0402 SMD; Power: 1/16W; Type: resistor; VPC: 1/16W; Vendor: Panasonic
R257 R258 = PAS,R,large: ALT_SYMBOLS: 0402_1mm; CCA: 67; DigiKey: P33.2LCT-ND; Family: passive; ICA_MFR_NAME: PANASONIC; ICA_PARTNUM: $$1785048$$ERJ-3GSYJ102; Index PN: 725; Install: Y; MFG: Panasonic; Material: chip; P/D_NUM: ERJ-2RKF33R2X; Part Number: ERJ-2RKF33R2X; Part Specific: RES 33.2 OHM 1/16W 1% 0402 SMD; Power: 1/16W; TOLERANCE: 1%; Type: resistor; VPC: 1/16W; Vendor: Panasonic
R549 = PAS,R,large: ALT_SYMBOLS: 0402_1mm; DigiKey: 311-4.99KLRCT-ND; Family: passive; Index PN: 1129; Lead Style: SMT; MFG: Yageo; Material: chip; P/D_NUM: RC0402FR-074K99L; Part Number: RC0402FR-074K99L; Part Specific: RES 4.99K OHM 1/10W 1% 0402 SMD; Type: resistor; VPC: 1/16W; Vendor: Yageo
R712 R713 = PAS,R,large: ALT_SYMBOLS: 0402_1mm; DigiKey: 311-10.0KLRCT-ND; Family: passive; Index PN: 680; Lead Style: SMT; MFG: Yageo; Material: chip; P/D_NUM: RC0402FR-0710KL; Part Number: RC0402FR-0710KL; Power: 1/16W; Tolerance: 1%; Type: resistor; VPC: 1/16W; Vendor: Yageo
TP22 TP23 TP217 = EM,TERM,TESTPOINT: Family: board feature; Index PN: 1145; Install: DNI; Lead Style: SMT; MFG: -- NOT A PART --; Type: pad pattern; Vendor: -- NOT A PART --
U12 = TMP_18: DigiKey: 296-18256-1-ND; Family: logic; Index PN: 1027; Lead Style: SMT; MFG: Texas Instruments; P/D_NUM: SN74AUP1G07DCKR; Part Number: SN74AUP1G07DCKR; Part Specific: IC BUFF/DVR LOW PWR N-INV SC705  open drain; Type: buffer
U15 = TIDLP,DLPC7540: MFG: Texas Instruments; Part Number: DLPC7540ZDC
U16 = TMP_4: DigiKey: 296-18256-1-ND; Family: logic; Index PN: 1027; Lead Style: SMT; MFG: Texas Instruments; P/D_NUM: SN74AUP1G07DCKR; Part Number: SN74AUP1G07DCKR; Part Specific: IC BUFF/DVR LOW PWR N-INV SC705  open drain; Type: buffer
U34 = INF,DRVR,I2C,TXS0102,1x: DigiKey: 296-21931-1-ND; DigiReel: 296-21931-6-ND; Family: interface; Index PN: 877; Lead Style: SMT; MFG: Texas Instruments; P/D_NUM: TXS0102DCU; Part Number: TXS0102DCU; Part Specific: IC VOLT-LEVEL TRANSLATOR 8-US8; Type: driver; Vendor: Texas Instruments
U53 U54 = ANA,LIGHTSENSOR,IR_RECVR: DigiKey: 751-1386-5-ND; Family: analog; Index PN: 1497; Lead Style: SMT; MFG: Vishay; Part Specific: IC IR RCVR MOD 38KHZ DOME RADIAL; Type: photosensor; Vendor: Vishay
C2 C6 = PAS,CAP,NP: DigiKey: 1276-3364-1-ND; DigiReel: 1276-3364-6-ND; Family: passive; Install: Y; Lead Style: SMT; MFG: Samsung; Material: x5r; P/D_NUM: CL32A107MPVNNNE; Part Number: CL32A107MPVNNNE; Part Specific: CAP CER 100UF 10V 20% X5R 1210; TOLERANCE: 20%; Type: capacitor; VPC: 10V; Vendor: Samsung
C5 C7 C27 = PAS,CAP,NP: CCA: 115; DigiKey: 587-2086-1-ND; DigiReel: 587-2086-6-ND; Family: passive; Index PN: 1406; Install: Y; Lead Style: SMT; MFG: Taiyo Yuden; Material: x5r; P/D_NUM: TMK325BJ226MM-T; Part Number: TMK325BJ226MM-T; Part Specific: CAP CER 22UF 25V X5R 1210; TOLERANCE: 20%; Type: capacitor; VPC: 25V; Vendor: Taiyo Yuden
C15 = PAS,CAP,NP: DigiKey: 587-1293-1-ND; DigiReel: 587-1293-6-ND; Family: passive; Index PN: 1638; Install: Y; Lead Style: SMT; MFG: Taiyo Yuden; Material: x5r; P/D_NUM: EMK212BJ225KG-T; Part Number: EMK212BJ225KG-T; Part Specific: CAP CER 2.2UF 16V 10% X5R 0805; TOLERANCE: 10%; Type: capacitor; VPC: 16V; Vendor: Taiyo Yuden
J2 = EM,CONN,USB,TYPE-AB: DigiKey: WM14336CT-ND; Family: electro/mechanical; Index PN: 1654; Lead Style: SMT; MFG: Molex; P/D_NUM: 0475901001; Part Number: 0475901001; Part Specific: CONN RCPT MICRO USB AB 5P SMD RA; Type: connector; Vendor: Molex
J12 J16 = EM,HDR,4P,1R,1x,picoblade: DigiKey: WM7608CT-ND; DigiReel: WM7608DKR-ND; Family: electro/mechanical; Index PN: 1523; Lead Style: SMT; MFG: Molex; Part Specific: CONN HEADER 4POS 1.25MM VERT SMD; Pin Cnt: 4; Pin Spacing: 1.25mm; Row Cnt: 1; Type: connector; Vendor: Molex
J22 J506 = EM,HDR,6P,1R,1x,B6B-EH: DigiKey: 455-1661-ND; DigiReel: ---; Family: electro/mechanical; Index PN: 1663; Lead Style: TH; MFG: JST; P/D_NUM: B6B-ZR(LF)(SN); Part Number: B6B-ZR(LF)(SN); Part Specific: CONN HEADER VERT 6POS 1.5MM; Pin Cnt: 6; Pin Spacing: 1.5mm; Row Cnt: 1; Type: header; Vendor: JST
L2 = PAS,INDUCTOR: DigiKey: ---; DigiReel: ---; Family: passive; Index PN: 1652; Lead Style: SMT; MFG: Coilcraft; Mouser: 994-LPS4018-332MRC; P/D_NUM: LPS4018-332MRC; Part Number: LPS4018-332MRC; Part Specific: INDUCTOR 3.3UH 20% 1.9A SMD; Type: inductor; VPC: 1.9A; Vendor: Coilcraft
R4 R5 = PAS,R,large: DigiKey: YAG3085CT-ND; DigiReel: YAG3085DKR-ND; Family: passive; ICA_MFR_NAME: PANASONIC; ICA_PARTNUM: $$1785048$$ERJ-3GSYJ102; Index PN: 1737; Install: Y; Lead Style: SMT; MFG: Yageo; Material: chip; P/D_NUM: RC0402FR-0727R4L; Part Number: RC0402FR-0727R4L; Part Specific: RES 27.4 OHM 1% 1/16W 0402 SMD; TOLERANCE: 1%; Type: resistor; VPC: 1/16W; Vendor: Yageo
R11 = PAS,R,large: ALT_SYMBOLS: 0402_1mm; DigiKey: P31.6KLCT-ND; DigiReel: P31.6KLDKR-ND; Family: passive; ICA_MFR_NAME: PANASONIC; ICA_PARTNUM: $$1785048$$ERJ-3GSYJ102; Index PN: 1336; Install: Y; Lead Style: SMT; MFG: Panasonic; P/D_NUM: ERJ-2RKF3162X; Part Number: ERJ-2RKF3162X; Part Specific: RES 31.6K OHM 1% 1/10W 0402 SMD; TOLERANCE: 1%; Type: resistor; VPC: 1/10W; Vendor: Panasonic
R13 = PAS,R,large: ALT_SYMBOLS: 0402_1mm; DigiKey: P0.0JCT-ND; DigiReel: P0.0JDKR-ND; Family: passive; ICA_MFR_NAME: PANASONIC; ICA_PARTNUM: $$1785048$$ERJ-3GSYJ102; Index PN: 687; Install: DNI; Lead Style: SMT; MFG: Panasonic; Material: chip; P/D_NUM: ERJ-2GE0R00X; Part Number: ERJ-2GE0R00X; Part Specific: RES 0.0 OHM 1/16W 0402 SMD; Power: 1/16W; Type: resistor; VPC: 1/16W; Vendor: Panasonic
U1 = PAS,DIODE,TVS,TPD2E2U06DRL,1x: DigiKey: 296-38361-1-ND; DigiReel: 296-38361-6-ND; Family: passive; Index PN: 1340; Lead Style: SMT; MFG: Texas Instruments; P/D_NUM: TPD2E2U06DRLR; Part Number: TPD2E2U06DRLR; Part Specific: TVS DIODE 5.5VWM 12.4VC 5SOT; Type: diode,tvs
U7 = PWR,SW,TPS2501,USB: DigiKey: 296-25151-1-ND; Family: power; Index PN: 1651; Lead Style: Smt; MFG: Texas Instruments; Part Specific: IC USB PWR SW W/BOOST CONV 10SON; Type: reg,switching; Vendor: Texas Instruments
U30 = MEM,EEPROM,24LCxx,ALT: DigiKey: AT24C64D-SSHM-TCT-ND; DigiReel: AT24C64D-SSHM-TDKR-ND; Family: memory; Index PN: 1582; Lead Style: SMT; MFG: Microchip Technologies; Part Specific: IC EEPROM 64K I2C 1MHZ 8SOIC; Type: eeprom; Vendor: Microchip Technologies

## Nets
GND: C2.1 C5.1 C6.1 C7.1 C14.2 C15.1 C27.1 C69.1 C70.1 C151.1 C231.1 C232.1 C298.1 C299.1 C321.1 C517.2 C670.2 C684.1 C697.1 C698.1 C700.1 C837.1 J2.5(GND) J2.6(C1) J2.7(C2) J2.8(C3) J2.9(C4) J6.1 J6.10 J9.2 J12.4 J16.4 J20.6 J21.1 J22.2 J23.1 J73.1 J74.4 J501.4 J501.6 J501.8 J501.10 J501.12 J501.14 J501.16 J501.18 J501.20 J503.1 J506.2 R11.2(N2) R36.2(N2) R90.1(N1) R95.1(N1) R96.1(N1) R97.1(N1) R99.1(N1) R100.1(N1) R101.1(N1) R103.1(N1) R105.2(N2) R106.2(N2) R113.1(N1) R114.1(N1) R123.2(N2) R148.2(N2) R149.2(N2) R157.2(N2) R210.2(N2) R523.2(N2) R712.2(N2) R713.2(N2) R714.2(N2) R715.2(N2) U1.4(GND) U7.2(PGND) U7.5(GND) U7.11(PAD) U12.3(GND) U15.A29(USB_XI) U15.L26(HWTEST_EN) U15.M26(ICTSE) U16.3(GND) U30.4(GND) U30.7(WP) U34.2(GND) U38.2(I) U38.3(GND) U39.3(GND) U53.2 U54.2 U500.2(GND) U502.2(GND) U503.4(GND) X1.2(NC1) X1.4(NC2) X2.2(NC1) X2.4(NC2) ; also on sheet 3 4 5 6 7 8 9 10 11 12 15 16 17 21 22 23 25 26
38MHz_I: C232.2 R118.1(N1) X2.1
38MHz_O: C231.2 R117.1(N1) X2.3
40MHz_CLK0: R669.2(N2) R706.1(N1) ; also on sheet 3
40MHz_I: C69.2 R30.1(N1) X1.1
40MHz_O: C70.2 R31.1(N1) X1.3
40MHz_Y0: R669.1(N1) U503.3(Y0)
40MHz_Y1: R655.1(N1) R656.1(N1) U503.8(Y1)
AWC0_DACCLK_0_1: U15.AE2(GPIO_66) ; also on sheet 12
AWC0_DACD_PWMB_0: U15.AD4(GPIO_68) ; also on sheet 12
AWC0_DACD_PWMB_1: U15.AD2(GPIO_70) ; also on sheet 12
AWC0_DACS_PWMA_0: U15.AF4(GPIO_67) ; also on sheet 12
AWC0_DACS_PWMA_1: U15.AD3(GPIO_69) ; also on sheet 12
AWC0_OUT_ENZ: U15.AE3(GPIO_65) ; also on sheet 12
AWC1_DACCLK_0_1: U15.AC5(GPIO_72) ; also on sheet 12
AWC1_DACD_PWMB_0: U15.AC2(GPIO_74) ; also on sheet 12
AWC1_DACD_PWMB_1: U15.AD5(GPIO_76) ; also on sheet 12
AWC1_DACS_PWMA_0: U15.AC4(GPIO_73) ; also on sheet 12
AWC1_DACS_PWMA_1: U15.AC1(GPIO_75) ; also on sheet 12
AWC1_OUT_ENZ: U15.AD1(GPIO_71) ; also on sheet 12
BT656_CLK: U15.K1(GPIO_87) ; also on sheet 3 26
BT656_DATA_0: U15.N4(GPIO_77) ; also on sheet 3 26
BT656_DATA_1: R549.1(N1) U15.N5(GPIO_78) ; also on sheet 3 26
BT656_DATA_2: U15.M1(GPIO_79) ; also on sheet 3 26
BT656_DATA_3: U15.M2(GPIO_80) ; also on sheet 3 26
BT656_DATA_4: U15.M4(GPIO_81) ; also on sheet 3 26
BT656_DATA_5: U15.M5(GPIO_82) ; also on sheet 3 26
BT656_DATA_6: U15.L2(GPIO_83) ; also on sheet 3 26
BT656_DATA_7: U15.L3(GPIO_84) ; also on sheet 3 26
BT656_DATA_8: U15.L4(GPIO_85) ; also on sheet 3 26
BT656_DATA_9: U15.L5(GPIO_86) ; also on sheet 3 26
CAMERA_SP4: J503.4 TP217.1(P1)
CW0_INDEX: U15.AE29(CW_INDEX) ; also on sheet 9
CW0_PWM_OUT: U15.AE30(CW_PWM) ; also on sheet 10
CW1_INDEX: R613.1(N1) R866.1(N1) ; also on sheet 9
CW1_PWM_OUT: U15.K28(GPIO_54) ; also on sheet 9
CW2_INDEX: R601.1(N1) R868.1(N1) ; also on sheet 9
CW2_PWM_OUT: U15.K29(GPIO_55) ; also on sheet 8
DAO_CLKOUT: R678.1(N1) ; also on sheet 3
DAO_DO_0: R676.1(N1) ; also on sheet 3
DAO_DO_1: R677.1(N1) ; also on sheet 3
DMD_DMUX: J502.2 R674.1(N1)
DMD_DMUX0: J502.1 ; also on sheet 17
DMD_DMUX1: J502.3
DMD_P1P8V_EN: R867.1(N1) ; also on sheet 17
DMD_PWR_EN: U15.R4(GPIO_17) ; also on sheet 17
EXT_ARSTZ: TP21.1(P1) U15.AF29(EXT_ARSTZ)
FE_3D_LR: R260.1(N1) ; also on sheet 3 15
GPIO_18: J87.2 U15.R5(GPIO_18)
GPIO_18_TST_PD: J76.3 J78.3 J87.3 J89.3 R157.1(N1)
GPIO_18_TST_PU: J76.1 J78.1 J87.1 J89.1 R156.1(N1)
GPIO_19: J89.2 U15.P1(GPIO_19)
GPIO_20: J76.2 U15.P2(GPIO_20)
GPIO_21: J78.2 U15.P3(GPIO_21)
GPIO_32: R124.2(N2) U15.Y4(GPIO_32)
GPIO_33: R127.2(N2) U15.Y2(GPIO_33)
GPIO_34: R675.2(N2) U15.Y1(GPIO_34)
GPIO_35: R676.2(N2) U15.G29(GPIO_35)
GPIO_36: R613.2(N2) R677.2(N2) U15.G30(GPIO_36)
GPIO_37: R601.2(N2) R678.2(N2) U15.H26(GPIO_37)
GPIO_38: R168.2(N2) R614.2(N2) U15.H27(GPIO_38)
GPIO_39: R169.2(N2) R615.2(N2) U15.H28(GPIO_39)
GPIO_40: R18.2(N2) U15.H29(GPIO_40)
GPIO_41: R19.2(N2) U15.H30(GPIO_41)
GPIO_42: R104.2(N2) U15.J26(GPIO_42)
GPIO_43: R870.2(N2) U15.J27(GPIO_43)
GPIO_44: R871.2(N2) U15.J29(GPIO_44)
GPIO_45: R679.2(N2) R866.2(N2) R867.2(N2) U15.J30(GPIO_45)
GPIO_46: J82.2 R680.2(N2) R868.2(N2) U15.K27(GPIO_46)
GPIO_59: J505.2 U15.AG1(GPIO_59)
GPIO_59B: J505.3 R710.2(N2) R711.2(N2)
HBT_CLKOUT: R169.1(N1) ; also on sheet 3
HBT_DO: R168.1(N1) ; also on sheet 3
HDMI_CEC: R234.1(N1) ; also on sheet 3 15
HEARTBEAT: R237.2(N2) U12.2(A) U15.AA3(GPIO_28)
HEARTBEAT_DRVR: R32.2(N2) U12.4(Y)
HEARTBEAT_LED: D15.1(CATHODE) R32.1(N1)
HOLD_BOOTZ: J9.1 R119.1(N1) U15.AE4(GPIO_64)
ICE_RSTZ: J501.15 R504.1(N1) U39.2(A)
ICTSEN: R113.2(N2) U15.K26(ICTSEN)
IIC0_SCL: J16.1 R147.1(N1) U15.E27(IIC0_SCL) ; also on sheet 4 5 15 26
IIC0_SDA: J16.2 R146.1(N1) U15.D29(IIC0_SDA) ; also on sheet 4 5 15 26
IIC1_SCL: J12.1 J21.4 R140.1(N1) U15.T2(GPIO_11) U30.6(SCL) ; also on sheet 15 26
IIC1_SDA: J12.2 J21.3 R139.1(N1) U15.T5(GPIO_12) U30.5(SDA) ; also on sheet 15 26
IIC2_SCL: R79.1(N1) R124.1(N1) U34.8(B1) ; also on sheet 12
IIC2_SDA: R78.1(N1) R127.1(N1) U34.1(B2) ; also on sheet 12
IIC_BUSY: R128.1(N1) TP6.1(P1) U15.V1(GPIO_58) ; also on sheet 3 4 5 15
IR0: J88.1 U53.1
IR0_PWR: C697.2 R257.1(N1) U53.3
IR1: J90.1 U54.1
IR1_PWR: C698.2 R258.1(N1) U54.3
LEDSEL_0: U15.AB3(GPIO_24) ; also on sheet 25
LEDSEL_1: U15.AB2(GPIO_25) ; also on sheet 25
LEDSEL_2: U15.AA5(GPIO_26) ; also on sheet 6 25
LEDSEL_3: U15.AA4(GPIO_27) ; also on sheet 25
LEDSEL_4: R237.1(N1) ; also on sheet 25
LL_FAULT: TP24.1(P1) U15.AB4(GPIO_23) U16.2(A)
LL_FAULT_DRVR: R40.2(N2) U16.4(Y)
LL_FAULT_LED: D6.1(CATHODE) R40.1(N1)
LMP_TXD: R710.1(N1) ; also on sheet 6
LMPCTRL: R712.1(N1) TP219.1(P1) U15.W4(GPIO_52) ; also on sheet 6 25
LMPSTAT: R713.1(N1) TP220.1(P1) U15.W3(GPIO_53) ; also on sheet 6
LMPSYNC: R261.1(N1) TP218.1(P1) U15.V5(GPIO_51) ; also on sheet 25
LVDS_VREFTEST: TP159.1(P1) U15.AF16(LVDS_VREFTEST)
MTR_ARSTZ: U15.AF27(MTR_ARSTZ) ; also on sheet 8 9 10
OCLKA: R635.2(N2) ; also on sheet 8 9 10
OCLKA_T: R635.1(N1) U15.AD30(OCLKA)
OSC_38MHz: R589.1(N1) R604.1(N1) U500.3(OUT)
OSC_40MHz: U502.3(OUT) U503.1(CLKIN)
P1P8V: R82.1(N1) R83.1(N1) R141.1(N1) U34.3(VCCA) ; also on sheet 7 10 22
P3P3V: C151.2 C298.2 C299.2 C321.2 C517.1 C670.1 C684.2 C700.2 C837.2 D6.2(ANODE) D15.2(ANODE) J12.3 J16.3 J21.2 J22.1 J23.3 J73.2 J74.3 J501.1 J501.2 J503.2 J506.1 R20.2(N2) R21.2(N2) R22.2(N2) R34.2(N2) R38.2(N2) R39.2(N2) R78.2(N2) R79.2(N2) R119.2(N2) R122.2(N2) R128.2(N2) R139.2(N2) R140.2(N2) R146.2(N2) R147.2(N2) R150.2(N2) R151.2(N2) R156.2(N2) R256.2(N2) R257.2(N2) R258.2(N2) R504.2(N2) R505.2(N2) R506.2(N2) R508.2(N2) R517.2(N2) R519.2(N2) R520.1(N1) R522.2(N2) R549.2(N2) R716.2(N2) R717.2(N2) R869.2(N2) U12.5(PWR) U16.5(PWR) U30.3(A2) U30.8(VCC) U34.7(VCCB) U38.5(VCC) U39.5(PWR) U500.1(EN) U500.4(VDD) U502.1(EN) U502.4(VDD) U503.2(1G) U503.6(VDD) ; also on sheet 4 6 7 8 9 10 11 12 15 16 21 22 25 26
P3P3V_SB: C14.1 C15.2 C27.2 L2.1 R13.2(N2) U7.3(IN) ; also on sheet 4 5 7 21
PAUX0: R260.2(N2) R261.2(N2) U15.AB5(GPIO_22)
PAUX7: R674.2(N2) U15.AA2(GPIO_29)
PAUX8: R235.2(N2) U15.AA1(GPIO_30)
PAUX9: R234.2(N2) U15.Y5(GPIO_31)
PM_ADDR_23: U15.AB28(GPIO_47) ; also on sheet 16
PMD_INTZ: U15.AD26(PMD_INTZ) ; also on sheet 8 9 10
POSENSE: U15.AE27(POSENSE) ; also on sheet 8 9 10 16 21
PRIMARY_PU: J82.1 R869.1(N1)
PROJ_ON_OD: U15.AG2(GPIO_63) ; also on sheet 21
PWM_IN0: J73.3 J74.2 J77.1
PWM_IN1: J73.4 J74.1 J79.1
PWM_OUT_BLED: U15.AF1(GPIO_61) ; also on sheet 25
PWM_OUT_GLED: J98.1 U15.AF2(GPIO_60) ; also on sheet 25
PWM_OUT_IRLED: U15.AG3(GPIO_62) ; also on sheet 25
PWM_OUT_RLED: J505.1 ; also on sheet 25
PWM_OUT_STD_0: U15.W2(GPIO_56) ; also on sheet 25
PWM_OUT_STD_1: U15.V2(GPIO_57) ; also on sheet 25
PWRGOOD: U15.AG30(PWRGOOD) U39.4(Y) ; also on sheet 21
REFCLKA_I: R29.2(N2) R30.2(N2) R655.2(N2) R706.2(N2) U15.AJ18(REFCLKA_I)
REFCLKA_O: R29.1(N1) R31.2(N2) R656.2(N2) U15.AK18(REFCLKA_O)
REFCLKB_I: R116.2(N2) R118.2(N2) R604.2(N2) U15.B16(REFCLKB_I)
REFCLKB_O: R116.1(N1) R117.2(N2) R589.2(N2) U15.A16(REFCLKB_O)
RTCK: J501.11 R506.1(N1) R507.2(N2)
SAS_CLK: U15.V4(GPIO_06) ; also on sheet 25
SAS_CSZ: U15.U1(GPIO_09) ; also on sheet 25
SAS_DI: U15.U4(GPIO_07) ; also on sheet 25
SAS_DO: U15.U2(GPIO_08) ; also on sheet 25
SAS_INTGTR_EN: J21.5 U15.V3(GPIO_10) ; also on sheet 25
SECONDARY_PD: J82.3 R210.1(N1)
SPI0_CIPO: J506.5 R36.1(N1) R716.1(N1) U15.AD29(SSP0_RXD) ; also on sheet 9 12
SPI0_CLK: J506.3 R109.1(N1) R123.1(N1) R715.1(N1) ; also on sheet 9 12
SPI0_CLK_T: R109.2(N2) U15.AD28(SSP0_CLK)
SPI0_COPI: J506.4 R34.1(N1) R110.1(N1) R714.1(N1) ; also on sheet 9 12
SPI0_COPI_T: R110.2(N2) U15.AD27(SSP0_TXD)
SPI0_CSZ_0: J506.6 R111.1(N1) R122.1(N1) R717.1(N1) ; also on sheet 9
SPI0_CSZ_0_T: R111.2(N2) U15.AB27(SSP0_CSZ_0)
SPI0_CSZ_1: R672.1(N1) ; also on sheet 12
SPI0_CSZ_2: R673.1(N1) ; also on sheet 9
SPI0_CSZ_3: U15.AC29(GPIO_50) ; also on sheet 9
SPI0_CSZ_4: U15.AC30(GPIO_49)
SPI1_CIPO: J22.5 R150.1(N1) U15.C16(GPIO_02) ; also on sheet 15
SPI1_CLK: J22.3 R148.1(N1) U15.E16(GPIO_00) ; also on sheet 15
SPI1_COPI: J22.4 R149.1(N1) U15.D16(GPIO_01) ; also on sheet 15
SPI1_CSZ_0: J22.6 R151.1(N1) U15.B15(GPIO_03) ; also on sheet 15
SPI1_CSZ_1: R38.1(N1) TP22.1(P1) U15.B17(GPIO_04)
SPI1_CSZ_2: R39.1(N1) TP23.1(P1) U15.A17(GPIO_05)
SPI2_BC_CSZ: R680.1(N1) ; also on sheet 26
SPI2_CIPO: R19.1(N1) R105.1(N1) ; also on sheet 3 26
SPI2_CLK: R18.1(N1) R106.1(N1) ; also on sheet 3 26
SPI2_COPI: R20.1(N1) R104.1(N1) ; also on sheet 3 26
SPI2_CSZ_0: R22.1(N1) R870.1(N1) ; also on sheet 3 26
SPI2_CSZ_1: R21.1(N1) R871.1(N1) ; also on sheet 3 26
SPI2_CSZ_2: R679.1(N1) ; also on sheet 3 26
TCK: J20.5 J501.9 R507.1(N1) R517.1(N1) U15.AK19(TCK) ; also on sheet 4
TDI: J20.2 J501.5 R519.1(N1) U15.AG20(TDI) ; also on sheet 4
TDO1: J20.4 U15.AG19(TDO1) ; also on sheet 4
TDO2: J501.13 R505.1(N1) U15.AH19(TDO2)
TMP_IIC2_SCL: R83.2(N2) U34.5(A1)
TMP_IIC2_SDA: R82.2(N2) U34.4(A2)
TMS1: J20.3 U15.AH20(TMS1) ; also on sheet 4
TMS2: J501.7 R508.1(N1) U15.AJ20(TMS2)
TMS3: R256.1(N1) U15.AK20(TMS3)
TRSTZ: R520.2(N2) U15.AG21(TRSTZ) U38.4(O)
TRSTZ_IN: J20.1 J501.3 R522.1(N1) R523.1(N1) U38.1(~{OE}) ; also on sheet 4
TSTPT_0: J6.2 R103.2(N2) U15.E29(TSTPT_0)
TSTPT_1: J6.3 R101.2(N2) U15.E30(TSTPT_1)
TSTPT_2: J6.4 R100.2(N2) U15.F26(TSTPT_2)
TSTPT_3: J6.5 R99.2(N2) U15.F27(TSTPT_3)
TSTPT_4: J6.6 R97.2(N2) U15.F28(TSTPT_4)
TSTPT_5: J6.7 R96.2(N2) U15.F29(TSTPT_5)
TSTPT_6: J6.8 R95.2(N2) U15.G26(TSTPT_6)
TSTPT_7: J6.9 R90.2(N2) U15.G28(TSTPT_7)
TXS_OE: R141.2(N2) U34.6(OE)
UART0_CTSZ: J23.2 U15.N3(UART0_CTSZ) ; also on sheet 11
UART0_RTSZ: J23.6 U15.N2(UART0_RTSZ) ; also on sheet 11
UART0_RXD: J23.5 U15.P5(UART0_RXD) ; also on sheet 11
UART0_TXD: J23.4 U15.P4(UART0_TXD) ; also on sheet 11
UART1_CTSZ: U15.R1(GPIO_15) ; also on sheet 11
UART1_RTSZ: U15.R2(GPIO_16) ; also on sheet 11
UART1_RXD: U15.T3(GPIO_14) ; also on sheet 11
UART1_TXD: U15.T4(GPIO_13) ; also on sheet 11
UART2_RXD: J98.2 R615.1(N1) ; also on sheet 11
UART2_TXD: R614.1(N1) R711.1(N1) ; also on sheet 11
USB_AUX: C5.2 R91.1(N1) U7.10(AUX)
USB_DAT_N: R4.1(N1) U15.A27(USB_DAT_N)
USB_DAT_N_IN: J2.2(DM) R4.2(N2) U1.5(IO2)
USB_DAT_P: R5.1(N1) U15.B27(USB_DAT_P)
USB_DAT_P_IN: J2.3(DP) R5.2(N2) U1.3(IO1)
USB_EN: R13.1(N1) R14.1(N1) U7.4(EN)
USB_ENUSB: R8.1(N1) U7.7(ENUSB)
USB_FAULTZ: R91.2(N2) TP9.1(P1) U7.8(~{FAULT})
USB_ID: J2.4(ID) TP286.1(P1) U15.C27(USB_ID)
USB_ILIM: R11.1(N1) U7.6(ILIM)
USB_OTG_CP_EN: R8.2(N2) R14.2(N2) U15.AB26(GPIO_48)
USB_SW: L2.2 U7.1(SW)
USB_TXRTUNE: R114.2(N2) U15.C26(USB_TXRTUNE)
USB_VBUS: C2.2 C6.2 C7.2 J2.1(VBUS) U7.9(USB) U15.D26(USB_VBUS)
VBIAS_MON: R235.1(N1) ; also on sheet 17
WRP_CAMERA_TRIG: J503.3 R675.1(N1)
N30083522: R673.2(N2) U15.AC28(SSP0_CSZ_2)
N30083525: R672.2(N2) U15.AC26(SSP0_CSZ_1)

Not connected (* = marked no-connect by the designer): J21 6; J501 17* 19*; U1 1(NC1)* 2(NC2)*; U12 1*; U15 AJ19(TDO3)* B29(USB_XO)* C28(USB_ANALOGTEST)* C30(ETM_TRACECLK)* D30(ETM_TRACECTL)*; U16 1*; U30 1(A0)* 2(A1)*; U39 1*; U503 5(NC2)* 7(NC1)*

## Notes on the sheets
sheet 18
- Crystal Load Capacitor Calculation:
  Die and Package capactance ~= 2.5pF
  PCB trace capacitance ~= 2pF
  Load capacitor requirement = 12pF
  Load capacitors = 2 * (12pF - 4.5pF) = 15pF
- JTAG
  BOUNDARY
  SCAN
- For Texas Instruments Development Only
- REALVIEW ICE JTAG I/F
- DLPC Clocks, JTAG, UART, USB, SPI0, Etc.
- (C) COPYRIGHT 2020
         Texas Instruments
        All Rights Reserved
sheet 19
- DLPC IS SECONDARY ON SPI1
- {DI at DLPC}
- {DO at DLPC}
- Projector Settings Memory
  I2C Address set to 0xA8
- WPC
    I/F
- {DI at DLPC}
- {DO at DLPC}
- USB, SPI, I2C Interfaces & EEPROM
- (C) COPYRIGHT 2020
         Texas Instruments
        All Rights Reserved
sheet 20
- {<-DI}
- {DO->}
- DLPC IS SECONDARY ON SPI1
- LL_FAULTz
- HEARTBEAT
- Primary/Secondary Selection
- Jumper installed -
  Hold in Boot Loader
- DLPC IS SECONDARY ON SPI1
- TILT SENSOR INPUT
- DLPC GPIO Connections
- (C) COPYRIGHT 2020
         Texas Instruments
        All Rights Reserved
